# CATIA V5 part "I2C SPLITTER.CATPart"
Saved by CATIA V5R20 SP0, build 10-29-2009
Part number: I2C SPLITTER
Revision: ---
Definition: AMAZON
Nomenclature: I2C SPLITTER
Source: bought
Description: I2C SPLITTER, (5) DF13C-4P-1.25
Property "Date": "09/02/18"
Property "Price": "$3.54"
Property "URL": "https://www.amazon.com/MonkeyJack-Splitter-Pixhawk-Controller-Accessories/dp/B075DBNHY6/"
Bounding box of the stored display mesh (mm): x -6 to 6, y -16.5 to 16.5, z 0 to 5.8
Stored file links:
  C:\Users\Admin\Desktop\I2C SPLITTER.CATPart
  C:\Users\Admin\Desktop\XRLM-A10001\PX4FLOW.CATPart
  C:\Users\Admin\Desktop\XRLM-A10001\Pixhawk.CATPart

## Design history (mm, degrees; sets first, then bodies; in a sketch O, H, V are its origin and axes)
Body1 (main body)
Body2 "Body.2"
  Sketch1 on xy-plane, origin (0, 0, 0), H (1, 0, 0), V (0, 1, 0)
    line L1 (6, 16.5) -> (6, -16.5)
    line L2 (6, -16.5) -> (-6, -16.5)
    line L3 (-6, -16.5) -> (-6, 16.5)
    line L4 (-6, 16.5) -> (6, 16.5)
    length L3 = 33
    length L4 = 12
    vertical: L1 V, L3 V
    horizontal: L2 H, L4 H
    equidistance: L1 L3 O, L2 L4 O
  Pad1: profile Sketch1, direction (0, 0, 1), length 1
  Sketch2 on end face of Pad1, origin (0, 0, 1), H (1, 0, 0), V (0, 1, 0)
    polyline C1
    polyline C2
    polyline C3
    polyline C4
    polyline C5
    polyline C6
    polyline C7
    polyline C8
    polyline C9
    polyline C10
    polyline C11
    polyline C12
    polyline C13
    polyline C14
    polyline C15
  Pad2: profile Sketch2, direction (0, 0, 1), length 0.0025
Body3 "Body.3"
  Solid1: solid without history
Body4 "Body.4"
  Solid2: solid without history
Body5 "Body.5"
  Solid3: solid without history
Body6 "Body.6"
  Solid4: solid without history
Body7 "Body.7"
  Solid5: solid without history
Body8 "Body.3"
  Solid6: solid without history
Body9 "Body.4"
  Solid7: solid without history
Body10 "Body.5"
  Solid8: solid without history
Body11 "Body.6"
  Solid9: solid without history
Body12 "Body.7"
  Solid10: solid without history
Body13 "Body.3"
  Solid11: solid without history
Body14 "Body.4"
  Solid12: solid without history
Body15 "Body.5"
  Solid13: solid without history
Body16 "Body.6"
  Solid14: solid without history
Body17 "Body.7"
  Solid15: solid without history
Body18 "Body.3"
  Solid16: solid without history
Body19 "Body.4"
  Solid17: solid without history
Body20 "Body.5"
  Solid18: solid without history
Body21 "Body.6"
  Solid19: solid without history
Body22 "Body.7"
  Solid20: solid without history
Body23 "Body.3"
  Solid21: solid without history
Body24 "Body.4"
  Solid22: solid without history
Body25 "Body.5"
  Solid23: solid without history
Body26 "Body.6"
  Solid24: solid without history
Body27 "Body.7"
  Solid25: solid without history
